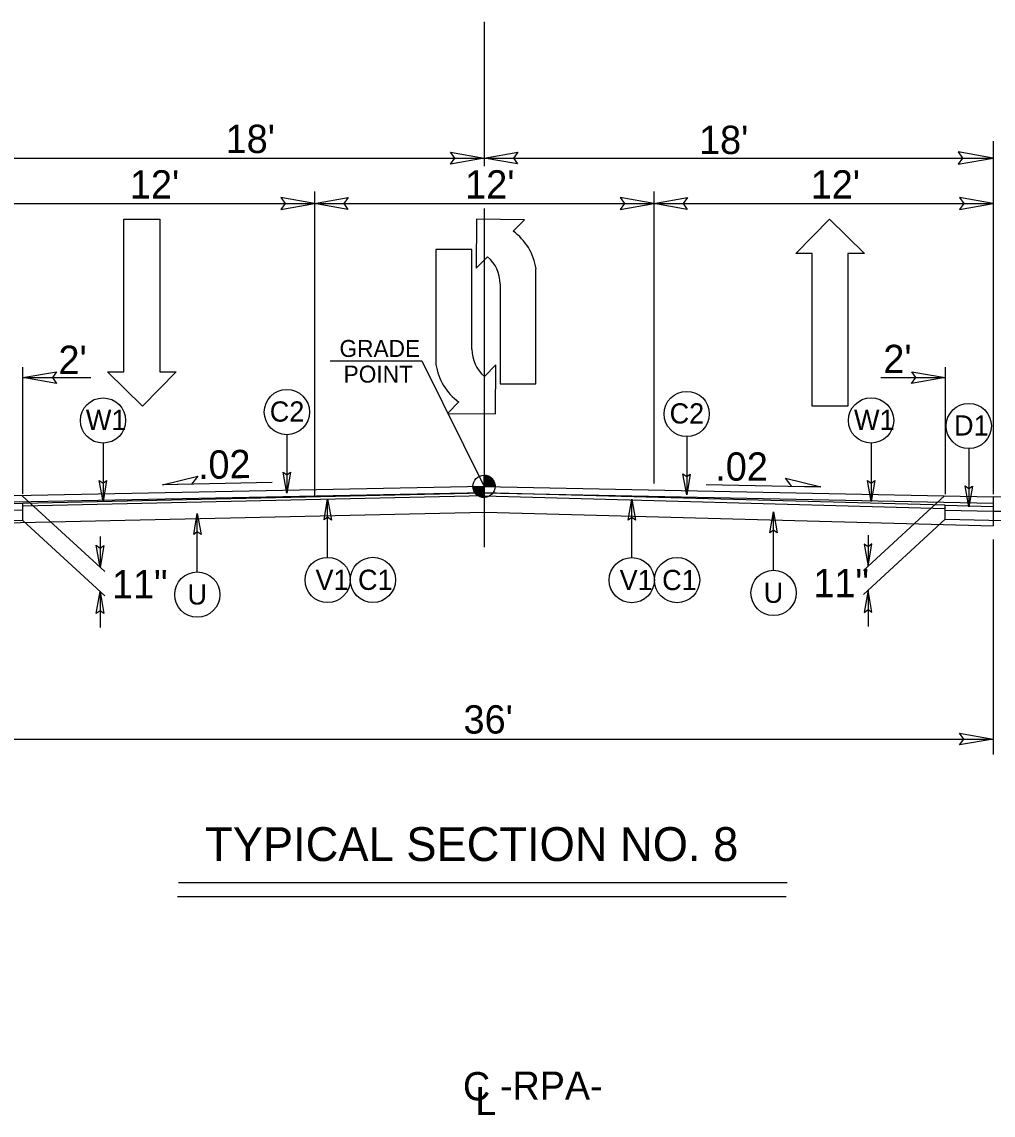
# Model space of a CAD drawing. Extents: x 957297 to 961629, y 830661 to 840840.
# Drawn here: x 959367.2 to 959634.8, y 836221.6 to 836522.8 of the extents above; entities that cross this region are included whole.
import ezdxf

# ---------------------------------------------------------------- set-up
doc = ezdxf.new("R2010")
doc.units = 0
for name, color, linetype in [('Default', 7, 'Continuous'), ('Old_Level_1', 7, 'Continuous'), ('Old_Level_11', 7, 'Continuous'), ('Old_Level_3', 7, 'Continuous'), ('Prop CMT Pvmt Milling', 7, 'Continuous'), ('Prop Dimension Text', 7, 'Continuous'), ('Prop Lane Arrow CELL', 7, 'Continuous'), ('Typical ID Circle CELL', 7, 'Continuous'), ('Typical Terminator CELL', 7, 'Continuous'), ('Typical Text Grade Point CELL', 7, 'Continuous'), ('Typical Text ID Circle CELL', 7, 'Continuous')]:
    doc.layers.add(name, color=color, linetype=linetype)

# ---------------------------------------------------------------- blocks, each defined once
blk = doc.blocks.new('Lane Arrow Left Turn')
at = {"layer": 'Prop Lane Arrow CELL'}
for p, q in [((0, 0), (-4.5, 0.05)), ((-4.5, 0.05), (-3.45, -1)), ((-0.05, -4.4), (0, 0)), ((-5.95, -2.15), (-15.1, -2.15)), ((-15.1, -2.15), (-15.1, -5.45)), ((-1.1, -3.35), (-0.05, -4.4)), ((-15.1, -5.45), (-4.55, -5.45))]:
    blk.add_line(p, q, dxfattribs=at)
for centre, radius, start, end in [((-5.94, 1.11), 3.27, 270, 319.6582), ((-5.34, -0.27), 5.25, 278.6761, 323.9878)]:
    blk.add_arc(centre, radius, start, end, dxfattribs=at)
blk = doc.blocks.new('Lane Arrow Through')
at = {"layer": 'Prop Lane Arrow CELL'}
for p, q in [((-3.15, 1.6), (-3.15, 3.1)), ((-3.15, 3.1), (0, 0)), ((-17.15, 1.6), (-3.15, 1.6)), ((-17.15, -1.7), (-17.15, 1.6)), ((0, 0), (-3.15, -3.2)), ((-3.15, -1.7), (-17.15, -1.7)), ((-3.15, -3.2), (-3.15, -1.7))]:
    blk.add_line(p, q, dxfattribs=at)

msp = doc.modelspace()

# ---------------------------------------------------------------- linework, layer by layer
at = {"layer": 'Default'}
for p, q in [((959494.54, 836522.77), (959494.54, 836483.04)), ((959494.54, 836471.39), (959494.54, 836378.09))]:
    msp.add_line(p, q, dxfattribs=at)
at = {"layer": 'Old_Level_1'}
for p, q in [((959634.76, 836489.88), (959634.76, 836392.65)), ((959354.32, 836485.26), (959494.54, 836485.26)), ((959494.54, 836485.26), (959634.76, 836485.26)), ((959447.8, 836476.07), (959447.8, 836395.58)), ((959447.8, 836476.07), (959447.8, 836392.17)), ((959541.28, 836476.07), (959541.28, 836395.6)), ((959634.76, 836476.07), (959634.76, 836393.04)), ((959354.32, 836472.72), (959447.8, 836472.72)), ((959447.8, 836472.72), (959541.28, 836472.72)), ((959541.28, 836472.72), (959634.76, 836472.72)), ((959367.52, 836392.8), (959367.52, 836427.7)), ((959621.56, 836427.7), (959621.56, 836392.65)), ((959367.52, 836424.77), (959386.23, 836424.77)), ((959603.78, 836424.77), (959621.56, 836424.77)), ((959494.54, 836394.81), (959494.54, 836397.87)), ((959494.54, 836394.81), (959494.54, 836397.87)), ((959494.54, 836394.81), (959354.32, 836391.97)), ((959436.13, 836395.86), (959405.92, 836395.26)), ((959491.48, 836394.81), (959494.54, 836394.81)), ((959491.48, 836394.81), (959494.54, 836394.81)), ((959497.6, 836394.81), (959494.54, 836394.81)), ((959494.54, 836391.76), (959494.54, 836394.81)), ((959494.54, 836394.81), (959494.54, 836391.76)), ((959494.54, 836394.81), (959634.76, 836391.97)), ((959497.6, 836394.81), (959494.54, 836394.81)), ((959494.54, 836391.76), (959494.54, 836394.81)), ((959494.54, 836394.81), (959494.54, 836391.76)), ((959555.7, 836395.3), (959587.3, 836394.67)), ((959494.54, 836393.08), (959354.32, 836390.24)), ((959367.34, 836392.23), (959390.03, 836371.35)), ((959494.54, 836393.08), (959634.76, 836390.24)), ((959621.37, 836392.24), (959599.05, 836371.7)), ((959367.52, 836388.26), (959354.32, 836387.99)), ((959367.52, 836385.41), (959367.52, 836390.19)), ((959621.56, 836385.76), (959621.56, 836389.62)), ((959621.56, 836388.26), (959634.76, 836387.99)), ((959634.76, 836389.26), (959634.76, 836383.94)), ((959367.52, 836385.41), (959331.2, 836384.68)), ((959367.52, 836385.41), (959390.03, 836364.7)), ((959621.56, 836385.76), (959599.05, 836365.05)), ((959621.56, 836385.76), (959657.52, 836385.03)), ((959388.77, 836381.02), (959388.77, 836372.51)), ((959600.31, 836381.37), (959600.31, 836372.86)), ((959634.76, 836380.21), (959634.76, 836320.96)), ((959388.75, 836365.88), (959388.75, 836355.92)), ((959600.33, 836366.22), (959600.33, 836356.27)), ((959354.32, 836325.24), (959634.76, 836325.24)), ((959578.04, 836285.59), (959410.34, 836285.59)), ((959577.76, 836281.79), (959410.06, 836281.79))]:
    msp.add_line(p, q, dxfattribs=at)
for points in [[(959494.58, 836397.87), (959494.58, 836397.87), (959494.58, 836394.81)], [(959494.58, 836397.87), (959494.58, 836397.87), (959494.58, 836394.81)], [(959494.63, 836397.87), (959494.63, 836394.81)], [(959494.63, 836397.87), (959494.63, 836394.81)], [(959494.69, 836397.87), (959494.69, 836394.81)], [(959494.69, 836397.87), (959494.69, 836394.81)], [(959494.76, 836397.86), (959494.76, 836394.81)], [(959494.76, 836397.86), (959494.76, 836394.81)], [(959494.82, 836397.86), (959494.82, 836394.81)], [(959494.82, 836397.86), (959494.82, 836394.81)], [(959494.88, 836397.86), (959494.88, 836394.81)], [(959494.88, 836397.86), (959494.88, 836394.81)], [(959494.94, 836397.84), (959494.94, 836394.81)], [(959494.94, 836397.84), (959494.94, 836394.81)], [(959495, 836397.84), (959495, 836394.81)], [(959495, 836397.84), (959495, 836394.81)], [(959495.06, 836397.82), (959495.06, 836394.81)], [(959495.06, 836397.82), (959495.06, 836394.81)], [(959495.12, 836397.82), (959495.12, 836394.81)], [(959495.12, 836397.82), (959495.12, 836394.81)], [(959495.19, 836397.81), (959495.19, 836394.81)], [(959495.19, 836397.81), (959495.19, 836394.81)], [(959495.25, 836397.79), (959495.25, 836394.81)], [(959495.25, 836397.79), (959495.25, 836394.81)], [(959495.31, 836397.77), (959495.31, 836394.81)], [(959495.31, 836397.77), (959495.31, 836394.81)], [(959495.37, 836397.75), (959495.37, 836394.81)], [(959495.37, 836397.75), (959495.37, 836394.81)], [(959495.44, 836397.74), (959495.44, 836394.81)], [(959495.44, 836397.74), (959495.44, 836394.81)], [(959495.49, 836397.71), (959495.49, 836394.81)], [(959495.49, 836397.71), (959495.49, 836394.81)], [(959495.56, 836397.7), (959495.55, 836394.81)], [(959495.56, 836397.7), (959495.55, 836394.81)], [(959495.61, 836397.68), (959495.61, 836394.81)], [(959495.61, 836397.68), (959495.61, 836394.81)], [(959495.67, 836397.66), (959495.67, 836394.81)], [(959495.67, 836397.66), (959495.67, 836394.81)], [(959495.74, 836397.63), (959495.74, 836394.81)], [(959495.74, 836397.63), (959495.74, 836394.81)], [(959495.8, 836397.61), (959495.8, 836394.81)], [(959495.8, 836397.61), (959495.8, 836394.81)], [(959495.86, 836397.57), (959495.86, 836394.81)], [(959495.86, 836397.57), (959495.86, 836394.81)], [(959495.91, 836397.55), (959495.91, 836394.81)], [(959495.91, 836397.55), (959495.91, 836394.81)], [(959495.97, 836397.52), (959495.97, 836394.81)], [(959495.97, 836397.52), (959495.97, 836394.81)], [(959496.04, 836397.49), (959496.04, 836394.81)], [(959496.04, 836397.49), (959496.04, 836394.81)], [(959496.1, 836397.45), (959496.1, 836394.81)], [(959496.1, 836397.45), (959496.1, 836394.81)], [(959496.16, 836397.41), (959496.16, 836394.81)], [(959496.16, 836397.41), (959496.16, 836394.81)], [(959496.23, 836397.37), (959496.23, 836394.81)], [(959496.23, 836397.37), (959496.23, 836394.81)], [(959496.29, 836397.32), (959496.29, 836394.81)], [(959496.29, 836397.32), (959496.29, 836394.81)], [(959496.34, 836397.29), (959496.34, 836394.81)], [(959496.34, 836397.29), (959496.34, 836394.81)], [(959496.41, 836397.24), (959496.41, 836394.81)], [(959496.41, 836397.24), (959496.41, 836394.81)], [(959496.47, 836397.19), (959496.47, 836394.81)], [(959496.47, 836397.19), (959496.47, 836394.81)], [(959496.53, 836397.15), (959496.53, 836394.81)], [(959496.53, 836397.15), (959496.53, 836394.81)], [(959496.59, 836397.08), (959496.59, 836394.81)], [(959496.59, 836397.08), (959496.59, 836394.81)], [(959491.5, 836394.81), (959491.5, 836394.49)], [(959491.5, 836394.81), (959491.5, 836394.49)], [(959491.56, 836394.81), (959491.56, 836394.12)], [(959491.56, 836394.81), (959491.56, 836394.12)], [(959491.62, 836394.81), (959491.62, 836393.9)], [(959491.62, 836394.81), (959491.62, 836393.9)], [(959491.68, 836394.81), (959491.68, 836393.72)], [(959491.68, 836394.81), (959491.68, 836393.72)], [(959491.75, 836394.81), (959491.75, 836393.58)], [(959491.75, 836394.81), (959491.75, 836393.58)], [(959491.81, 836394.81), (959491.81, 836393.45)], [(959491.81, 836394.81), (959491.81, 836393.45)], [(959491.87, 836394.81), (959491.87, 836393.33)], [(959491.87, 836394.81), (959491.87, 836393.33)], [(959491.93, 836394.81), (959491.93, 836393.22)], [(959491.93, 836394.81), (959491.93, 836393.22)], [(959492, 836394.81), (959492, 836393.14)], [(959492, 836394.81), (959492, 836393.14)], [(959492.06, 836394.81), (959492.06, 836393.04)], [(959492.06, 836394.81), (959492.06, 836393.04)], [(959492.12, 836394.81), (959492.12, 836392.95)], [(959492.12, 836394.81), (959492.12, 836392.95)], [(959492.18, 836394.81), (959492.18, 836392.88)], [(959492.18, 836394.81), (959492.18, 836392.88)], [(959492.24, 836394.81), (959492.24, 836392.82)], [(959492.24, 836394.81), (959492.24, 836392.82)], [(959492.29, 836394.81), (959492.29, 836392.74)], [(959492.29, 836394.81), (959492.29, 836392.74)], [(959492.35, 836394.81), (959492.35, 836392.67)], [(959492.35, 836394.81), (959492.35, 836392.67)], [(959492.42, 836394.81), (959492.42, 836392.62)], [(959492.42, 836394.81), (959492.42, 836392.62)], [(959492.48, 836394.81), (959492.48, 836392.57)], [(959492.48, 836394.81), (959492.48, 836392.57)], [(959492.54, 836394.81), (959492.54, 836392.5)], [(959492.54, 836394.81), (959492.54, 836392.5)], [(959492.6, 836394.81), (959492.6, 836392.46)], [(959492.6, 836394.81), (959492.6, 836392.46)], [(959492.67, 836394.81), (959492.67, 836392.4)], [(959492.67, 836394.81), (959492.67, 836392.4)], [(959492.72, 836394.81), (959492.72, 836392.36)], [(959492.72, 836394.81), (959492.72, 836392.36)], [(959492.79, 836394.81), (959492.79, 836392.31)], [(959492.79, 836394.81), (959492.79, 836392.31)], [(959492.85, 836394.81), (959492.85, 836392.28)], [(959492.85, 836394.81), (959492.85, 836392.28)], [(959492.91, 836394.81), (959492.91, 836392.22)], [(959492.91, 836394.81), (959492.91, 836392.22)], [(959492.98, 836394.81), (959492.98, 836392.19)], [(959492.98, 836394.81), (959492.98, 836392.19)], [(959493.04, 836394.81), (959493.04, 836392.15)], [(959493.04, 836394.81), (959493.04, 836392.15)], [(959493.1, 836394.81), (959493.1, 836392.12)], [(959493.1, 836394.81), (959493.1, 836392.12)], [(959493.15, 836394.81), (959493.15, 836392.1)], [(959493.15, 836394.81), (959493.15, 836392.1)], [(959493.21, 836394.81), (959493.21, 836392.06)], [(959493.21, 836394.81), (959493.21, 836392.06)], [(959493.28, 836394.81), (959493.28, 836392.03)], [(959493.28, 836394.81), (959493.28, 836392.03)], [(959493.34, 836394.81), (959493.34, 836392.01)], [(959493.34, 836394.81), (959493.34, 836392.01)], [(959493.4, 836394.81), (959493.4, 836391.97)], [(959493.4, 836394.81), (959493.4, 836391.97)], [(959493.46, 836394.81), (959493.46, 836391.96)], [(959493.46, 836394.81), (959493.46, 836391.96)], [(959493.52, 836394.81), (959493.52, 836391.94)], [(959493.52, 836394.81), (959493.52, 836391.94)], [(959493.58, 836394.81), (959493.58, 836391.91)], [(959493.58, 836394.81), (959493.58, 836391.91)], [(959493.64, 836394.81), (959493.64, 836391.9)], [(959493.64, 836394.81), (959493.64, 836391.9)], [(959493.7, 836394.81), (959493.7, 836391.87)], [(959493.7, 836394.81), (959493.7, 836391.87)], [(959493.76, 836394.81), (959493.76, 836391.86)], [(959493.76, 836394.81), (959493.76, 836391.86)], [(959493.83, 836394.81), (959493.83, 836391.85)], [(959493.83, 836394.81), (959493.83, 836391.85)], [(959493.89, 836394.81), (959493.89, 836391.83)], [(959493.89, 836394.81), (959493.89, 836391.83)], [(959493.95, 836394.81), (959493.95, 836391.81)], [(959493.95, 836394.81), (959493.95, 836391.81)], [(959494.01, 836394.81), (959494.01, 836391.81)], [(959494.01, 836394.81), (959494.01, 836391.81)], [(959494.07, 836394.81), (959494.07, 836391.8)], [(959494.07, 836394.81), (959494.07, 836391.8)], [(959494.13, 836394.81), (959494.13, 836391.78)], [(959494.13, 836394.81), (959494.13, 836391.78)], [(959494.2, 836394.81), (959494.2, 836391.78)], [(959494.2, 836394.81), (959494.2, 836391.78)], [(959494.26, 836394.81), (959494.26, 836391.78)], [(959494.26, 836394.81), (959494.26, 836391.78)], [(959494.32, 836394.81), (959494.32, 836391.76)], [(959494.32, 836394.81), (959494.32, 836391.76)], [(959494.38, 836394.81), (959494.38, 836391.76)], [(959494.38, 836394.81), (959494.38, 836391.76)], [(959494.43, 836394.81), (959494.43, 836391.76)], [(959494.43, 836394.81), (959494.43, 836391.76)], [(959494.49, 836394.81), (959494.49, 836391.76), (959494.49, 836391.76)], [(959494.49, 836394.81), (959494.49, 836391.76), (959494.49, 836391.76)], [(959496.65, 836397.02), (959496.65, 836394.81)], [(959496.65, 836397.02), (959496.65, 836394.81)], [(959496.72, 836396.96), (959496.72, 836394.81)], [(959496.72, 836396.96), (959496.72, 836394.81)], [(959496.77, 836396.9), (959496.77, 836394.81)], [(959496.77, 836396.9), (959496.77, 836394.81)], [(959496.83, 836396.84), (959496.83, 836394.81)], [(959496.83, 836396.84), (959496.83, 836394.81)], [(959496.89, 836396.77), (959496.89, 836394.81)], [(959496.89, 836396.77), (959496.89, 836394.81)], [(959496.95, 836396.68), (959496.95, 836394.81)], [(959496.95, 836396.68), (959496.95, 836394.81)], [(959497.02, 836396.61), (959497.02, 836394.81)], [(959497.02, 836396.61), (959497.02, 836394.81)], [(959497.08, 836396.52), (959497.08, 836394.81)], [(959497.08, 836396.52), (959497.08, 836394.81)], [(959497.14, 836396.43), (959497.14, 836394.81)], [(959497.14, 836396.43), (959497.14, 836394.81)], [(959497.2, 836396.32), (959497.2, 836394.81)], [(959497.2, 836396.32), (959497.2, 836394.81)], [(959497.26, 836396.22), (959497.26, 836394.81)], [(959497.26, 836396.22), (959497.26, 836394.81)], [(959497.32, 836396.07), (959497.32, 836394.81)], [(959497.32, 836396.07), (959497.32, 836394.81)], [(959497.39, 836395.93), (959497.39, 836394.81)], [(959497.39, 836395.93), (959497.39, 836394.81)], [(959497.45, 836395.77), (959497.45, 836394.81)], [(959497.45, 836395.77), (959497.45, 836394.81)], [(959497.51, 836395.56), (959497.51, 836394.81)], [(959497.51, 836395.56), (959497.51, 836394.81)], [(959497.57, 836395.25), (959497.57, 836394.81)], [(959497.57, 836395.25), (959497.57, 836394.81)], [(959354.32, 836389.89), (959367.52, 836390.19)], [(959621.56, 836389.62), (959634.76, 836389.26)], [(959354.32, 836384.56), (959494.7, 836387.76)], [(959494.7, 836387.76), (959634.76, 836383.94)]]:
    msp.add_lwpolyline(points, dxfattribs=at)
msp.add_circle((959494.54, 836394.82), 3.06, dxfattribs=at)
msp.add_circle((959494.54, 836394.82), 3.06, dxfattribs=at)
for start, end in [(359.9905, 89.9905), (359.9905, 89.9905), (179.9905, 269.9905), (179.9905, 269.9905)]:
    msp.add_arc((959494.54, 836394.82), 3.06, start, end, dxfattribs=at)
at = {"layer": 'Old_Level_11'}
for p, q in [((959405.92, 836395.26), (959415.67, 836397.68)), ((959415.67, 836397.68), (959413.94, 836395.42)), ((959579.3, 836394.83), (959577.56, 836397.09)), ((959577.56, 836397.09), (959587.3, 836394.67)), ((959413.94, 836395.42), (959405.92, 836395.26)), ((959587.3, 836394.67), (959579.3, 836394.83))]:
    msp.add_line(p, q, dxfattribs=at)
msp.add_lwpolyline([(959625.15, 836483.6), (959634.76, 836485.26), (959625.1, 836486.97), (959626.32, 836485.26)], close=True, dxfattribs=at)
at = {"layer": 'Old_Level_3'}
for p, q in [((959646.3, 836391.4), (959634.76, 836391.97)), ((959634.76, 836391.97), (959634.76, 836387.99)), ((959634.76, 836387.99), (959651.33, 836387.99))]:
    msp.add_line(p, q, dxfattribs=at)
at = {"layer": 'Prop CMT Pvmt Milling'}
for p, q in [((959367.52, 836390.19), (959494.54, 836393.08)), ((959494.54, 836393.08), (959494.54, 836392.21)), ((959494.54, 836392.21), (959621.56, 836388.75)), ((959367.52, 836389.33), (959367.52, 836390.19))]:
    msp.add_line(p, q, dxfattribs=at)
for points in [[(959494.54, 836393.08), (959494.54, 836392.21), (959367.52, 836389.33)], [(959621.56, 836388.75), (959621.56, 836389.62), (959494.54, 836393.08)]]:
    msp.add_lwpolyline(points, dxfattribs=at)
at = {"layer": 'Typical ID Circle CELL'}
for p, q in [((959389.57, 836406.75), (959389.57, 836390.66)), ((959440.21, 836409.07), (959440.21, 836392.98)), ((959550.35, 836408.54), (959550.35, 836392.46)), ((959601.14, 836406.75), (959601.14, 836390.67)), ((959628.05, 836405.24), (959628.05, 836389.15)), ((959451.44, 836375.27), (959451.44, 836391.36)), ((959535.23, 836375.22), (959535.23, 836391.3)), ((959415.54, 836371.25), (959415.54, 836387.33)), ((959574.27, 836371.7), (959574.27, 836387.79))]:
    msp.add_line(p, q, dxfattribs=at)
for centre in [(959440.21, 836415.29), (959389.57, 836412.97), (959550.35, 836414.77), (959601.14, 836412.98), (959628.05, 836411.46), (959451.44, 836369.05), (959463.91, 836369.07), (959535.23, 836368.99), (959547.7, 836369.01), (959415.54, 836365.02), (959574.27, 836365.48)]:
    msp.add_circle(centre, 6.23, dxfattribs=at)
at = {"layer": 'Typical Terminator CELL'}
for points in [[(959485.32, 836486.85), (959494.54, 836485.26), (959485.27, 836483.62), (959486.44, 836485.26)], [(959503.76, 836483.67), (959494.54, 836485.26), (959503.81, 836486.9), (959502.63, 836485.26)], [(959438.58, 836471.13), (959447.8, 836472.72), (959438.53, 836474.36), (959439.7, 836472.72)], [(959438.58, 836471.13), (959447.8, 836472.72), (959438.53, 836474.36), (959439.7, 836472.72)], [(959457.02, 836471.13), (959447.8, 836472.72), (959457.07, 836474.36), (959455.89, 836472.72)], [(959457.02, 836471.13), (959447.8, 836472.72), (959457.07, 836474.36), (959455.89, 836472.72)], [(959532.06, 836471.13), (959541.28, 836472.72), (959532.01, 836474.36), (959533.18, 836472.72)], [(959550.5, 836471.13), (959541.28, 836472.72), (959550.55, 836474.36), (959549.37, 836472.72)], [(959625.54, 836471.13), (959634.76, 836472.72), (959625.49, 836474.36), (959626.66, 836472.72)], [(959625.54, 836471.13), (959634.76, 836472.72), (959625.49, 836474.36), (959626.66, 836472.72)], [(959376.75, 836423.18), (959367.52, 836424.77), (959376.8, 836426.41), (959375.62, 836424.77)], [(959612.33, 836426.36), (959621.56, 836424.77), (959612.28, 836423.13), (959613.46, 836424.77)], [(959441.2, 836398.75), (959440.21, 836392.98), (959439.18, 836398.78), (959440.21, 836398.04)], [(959551.34, 836398.22), (959550.35, 836392.46), (959549.32, 836398.25), (959550.35, 836397.52)], [(959390.56, 836396.42), (959389.57, 836390.66), (959388.54, 836396.45), (959389.57, 836395.72)], [(959602.14, 836396.43), (959601.14, 836390.67), (959600.12, 836396.46), (959601.14, 836395.73)], [(959629.04, 836394.91), (959628.05, 836389.15), (959627.02, 836394.95), (959628.05, 836394.21)], [(959450.45, 836385.59), (959451.44, 836391.36), (959452.47, 836385.56), (959451.44, 836386.3)], [(959534.24, 836385.54), (959535.23, 836391.3), (959536.25, 836385.51), (959535.23, 836386.24)], [(959414.55, 836381.57), (959415.54, 836387.33), (959416.57, 836381.54), (959415.54, 836382.27)], [(959573.27, 836382.02), (959574.27, 836387.79), (959575.29, 836381.99), (959574.27, 836382.73)], [(959389.81, 836378.58), (959388.77, 836372.51), (959387.69, 836378.61), (959388.77, 836377.84)], [(959599.27, 836378.93), (959600.31, 836372.86), (959601.39, 836378.96), (959600.31, 836378.18)], [(959387.71, 836359.81), (959388.75, 836365.88), (959389.83, 836359.77), (959388.75, 836360.55)], [(959601.37, 836360.16), (959600.33, 836366.22), (959599.25, 836360.12), (959600.33, 836360.9)], [(959625.54, 836326.83), (959634.76, 836325.24), (959625.49, 836323.6), (959626.66, 836325.24)]]:
    msp.add_lwpolyline(points, close=True, dxfattribs=at)
at = {"layer": 'Typical Text Grade Point CELL'}
for p, q in [((959452.1, 836429.36), (959477.43, 836429.36)), ((959452.1, 836429.36), (959477.43, 836429.36)), ((959477.43, 836429.36), (959494.54, 836394.8)), ((959477.43, 836429.36), (959494.54, 836394.8))]:
    msp.add_line(p, q, dxfattribs=at)

# ---------------------------------------------------------------- block references
at = {"layer": 'Old_Level_1', "xscale": 3, "yscale": 3}
for name, p, rotation in [('Lane Arrow Through', (959400.41, 836416.96), -90.00000000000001), ('Lane Arrow Left Turn', (959492.48, 836468.41), 90), ('Lane Arrow Through', (959589.68, 836468.41), 90), ('Lane Arrow Left Turn', (959497.64, 836414.78), -90.00000000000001)]:
    msp.add_blockref(name, p, dxfattribs=dict(at, rotation=rotation))

# ---------------------------------------------------------------- texts
at = {"layer": 'Old_Level_1'}
msp.add_text('TYPICAL SECTION NO. 8', height=9.3239, dxfattribs=at).set_placement((959417.68, 836291.63))
at = {"layer": 'Old_Level_11'}
for s, p in [('GRADE', (959454.71, 836430.48)), ('POINT', (959455.84, 836423.41))]:
    msp.add_text(s, height=4.671, dxfattribs=at).set_placement(p)
at = {"layer": 'Prop Dimension Text'}
for s, height, rotation, p in [("18'", 7.801, 0, (959423.34, 836486.64)), ("18'", 7.801, 0, (959553.74, 836486.37)), ("12'", 7.801, 0, (959396.97, 836474.1)), ("12'", 7.801, 0, (959489.32, 836474.1)), ("12'", 7.801, 0, (959584.5, 836474.1)), ("2'", 7.801, 0, (959377.3, 836425.79)), ("2'", 7.801, 0, (959604.51, 836426.02)), ('.02', 7.801, 1.1839, (959415.79, 836396.84)), ('.02', 7.801, 360, (959558.21, 836396.39)), ('11"', 7.801, 0, (959392.03, 836363.98)), ('11"', 7.801, 0, (959585.24, 836364.29)), ("36'", 7.801, 0, (959488.87, 836326.74)), ('C', 7.77, 0, (959488.71, 836225.73)), ('-RPA- ', 7.767, 0, (959498.92, 836225.88)), ('L', 7.77, 0, (959492.11, 836221.64))]:
    msp.add_text(s, height=height, rotation=rotation, dxfattribs=at).set_placement(p)
at = {"layer": 'Typical Text ID Circle CELL'}
for s, height, p in [('C2', 5.572, (959435.5, 836412.66)), ('W1', 5.572, (959384.85, 836410.34)), ('C2', 5.572, (959545.64, 836412.14)), ('W1', 5.572, (959596.43, 836410.35)), ('D1', 5.572, (959623.99, 836408.83)), ('V1', 5.572, (959448.1, 836366.31)), ('C1', 5.572, (959459.81, 836366.31)), ('V1', 5.572, (959531.88, 836366.25)), ('C1', 5.572, (959543.59, 836366.25)), ('U', 5.57, (959412.84, 836362.28)), ('U', 5.57, (959571.56, 836362.74))]:
    msp.add_text(s, height=height, dxfattribs=at).set_placement(p)

doc.saveas('drawing.dxf')
